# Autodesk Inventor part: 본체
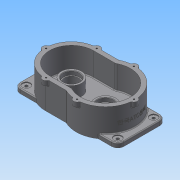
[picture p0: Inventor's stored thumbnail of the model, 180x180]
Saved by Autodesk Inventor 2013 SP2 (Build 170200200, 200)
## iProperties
Created: 2025-09
Part Number: 본체
Material: Generic
Document SubType Name: Modeling
Designer: a
Density: 1 g/cm^3
Author: a
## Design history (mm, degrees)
sketch "스케치1"
  geometry: L1 (-104.5, -55)-(104.5, -55); L2 (118.5, -41)-(118.5, 41); L3 (104.5, 55)-(-104.5, 55); L4 (-118.5, 41)-(-118.5, -41); L5 (-118.5, -55)-(118.5, 55); L6 (118.5, -55)-(-118.5, 55); A1 r 14 centre (-104.5, 41) between (-104.5, 55) and (-118.5, 41); A2 r 14 centre (104.5, 41) between (118.5, 41) and (104.5, 55); A3 r 14 centre (104.5, -41) between (104.5, -55) and (118.5, -41); A4 r 14 centre (-104.5, -41) between (-118.5, -41) and (-104.5, -55); 1 further point
  constraints: 12 end point, 8 point on circle, 8 point on line, 8 tangent, 4 centre point, 2 equal radius, 2 midpoint, 2 parallel, 1 horizontal, 1 perpendicular
  dimensions: "d0" = 237 distance of L5.end L6.end; "d2" = 110 distance of L6.start L5.end; "d3" = 14 radius of A1; "d4" = 14 radius of A2
extrude "돌출1" new body sketch "스케치1" distance "d5" = 10; taper "d6" = 0 deg
sketch "스케치2"
  geometry: L1 (118.5, 41)-(118.5, -41) reference; L2 (104.5, -55)-(-104.5, -55) reference; L3 (-118.5, -41)-(-118.5, 41) reference; L4 (-104.5, 55)-(104.5, 55) reference; L5 (-42.5, 50)-(8.132, 50); L6 (-42.5, -50)-(8.132, -50); L7 (-42.5, 60)-(5.684, 60); L8 (5.684, -60)-(-42.5, -60); A1 r 14 centre (104.5, 41) between (118.5, 41) and (104.5, 55) reference; A2 r 14 centre (104.5, -41) between (104.5, -55) and (118.5, -41) reference; A3 r 14 centre (-104.5, -41) between (-118.5, -41) and (-104.5, -55) reference; A4 r 14 centre (-104.5, 41) between (-104.5, 55) and (-118.5, 41) reference; A5 r 57 centre (35.5, 0) between (8.132, -50) and (8.132, 50); A6 r 50 centre (-42.5, 0) between (-42.5, 50) and (-42.5, -50); A7 r 60 centre (-42.5, 0) between (-42.5, 60) and (-42.5, -60); A8 r 67 centre (35.5, 0) between (5.684, -60) and (5.684, 60); 1 further point
  constraints: 8 end point, 8 point on circle, 4 centre point, 3 parallel, 2 horizontal alignment, 2 tangent, 3 other
  dimensions: "d7" = 114 diameter of A5; "d10" = 100 diameter of A6; "d11" = 76 distance from line of A6.centre L3; "d12" = 78 distance of A5.centre A6.centre; "d13" = 10 distance between parallel lines of L7 L5
  node "절단 모서리 투영1"
extrude "돌출2" join sketch "스케치2" distance "d14" = 64; taper "d15" = 0 deg
sketch "스케치3"
  geometry: L1 (8.132, 50)-(-42.5, 50) reference; L2 (-42.5, -50)-(8.132, -50) reference; L3 (118.5, 41)-(118.5, -41) reference; L4 (104.5, -55)-(73.762, -55) reference; L5 (5.684, -60)-(-42.5, -60) reference; L6 (-66.479, -55)-(-104.5, -55) reference; L7 (-118.5, -41)-(-118.5, 41) reference; L8 (-104.5, 55)-(-66.479, 55) reference; L9 (73.762, 55)-(104.5, 55) reference; L10 (-42.5, 60)-(5.684, 60) reference; L11 (50.467, -55)-(20.533, -55) reference; L12 (20.533, 55)-(50.467, 55) reference; C1 r 23.5 at (-42.5, 0); C2 r 23.5 at (35.5, 0); A1 r 50 centre (-42.5, 0) between (-42.5, 50) and (-42.5, -50) reference; A2 r 14 centre (104.5, 41) between (118.5, 41) and (104.5, 55) reference; A3 r 14 centre (104.5, -41) between (104.5, -55) and (118.5, -41) reference; A4 r 67 centre (35.5, 0) between (5.684, -60) and (73.762, -55) reference; A5 r 60 centre (-42.5, 0) between (-66.479, -55) and (-42.5, -60) reference; A6 r 14 centre (-104.5, -41) between (-118.5, -41) and (-104.5, -55) reference; A7 r 14 centre (-104.5, 41) between (-104.5, 55) and (-118.5, 41) reference; A8 r 60 centre (-42.5, 0) between (-66.479, 55) and (-66.479, -55) reference; A9 r 67 centre (35.5, 0) between (73.762, 55) and (5.684, 60) reference; A10 r 60 centre (-42.5, 0) between (-42.5, 60) and (-66.479, 55) reference; A11 r 67 centre (35.5, 0) between (73.762, -55) and (73.762, 55) reference; A12 r 57 centre (35.5, 0) between (8.132, -50) and (20.533, -55) reference; A13 r 57 centre (35.5, 0) between (20.533, -55) and (50.467, -55) reference; A14 r 57 centre (35.5, 0) between (50.467, -55) and (50.467, 55) reference; A15 r 57 centre (35.5, 0) between (50.467, 55) and (20.533, 55) reference; A16 r 57 centre (35.5, 0) between (20.533, 55) and (8.132, 50) reference; 1 further point
  constraints: 2 centre point, 2 coincident
  dimensions: "d16" = 47 diameter of C1; "d17" = 47 diameter of C2
  node "절단 모서리 투영2"
extrude "돌출3" join sketch "스케치3" distance "d18" = 12; taper "d19" = 0 deg
extrude "돌출4" join sketch "스케치2" distance "d20" = 10; taper "d21" = 0 deg
extrude "돌출5" join sketch "스케치3" distance "d22" = 26; taper "d23" = 0 deg
hole "구멍1" diameter "d26" = 6.6; stored, may be unused: countersink angle "d30" = 90 deg, drill point angle "d32" = 118 deg; dims "d24" = 10, "d25" = 10, "d27" = 6, "d28" = 18, "d29" = 2, "d31" = 8
hole "구멍2" diameter "d35" = 6.6; stored, may be unused: countersink angle "d39" = 90 deg, drill point angle "d41" = 118 deg; dims "d33" = 10, "d34" = 10, "d36" = 6, "d37" = 18, "d38" = 2, "d40" = 8
hole "구멍3" diameter "d44" = 6.6; stored, may be unused: countersink angle "d48" = 90 deg, drill point angle "d50" = 118 deg; dims "d42" = 10, "d43" = 10, "d45" = 6, "d46" = 18, "d47" = 2, "d49" = 8
hole "구멍4" diameter "d53" = 6.6; stored, may be unused: countersink angle "d57" = 90 deg, drill point angle "d59" = 118 deg; dims "d51" = 10, "d52" = 10, "d54" = 6, "d55" = 18, "d56" = 2, "d58" = 8
hole "구멍5" diameter "d62" = 32; stored, may be unused: countersink angle "d66" = 90 deg, drill point angle "d68" = 0 deg; dims "d63" = 6, "d64" = 37, "d65" = 9, "d67" = 16, "d69" = 10, "d70" = 10
hole "구멍6" diameter "d73" = 28; stored, may be unused: countersink angle "d77" = 90 deg, drill point angle "d79" = 0 deg; dims "d71" = 10, "d72" = 10, "d74" = 6, "d75" = 4, "d76" = 2, "d78" = 3
hole "구멍7" diameter "d82" = 28; stored, may be unused: countersink angle "d86" = 90 deg, drill point angle "d88" = 0 deg; dims "d80" = 10, "d81" = 10, "d83" = 6, "d84" = 37, "d85" = 9, "d87" = 30
hole "구멍8" diameter "d91" = 35; stored, may be unused: countersink angle "d95" = 90 deg, drill point angle "d97" = 0 deg; dims "d89" = 10, "d90" = 10, "d92" = 6, "d93" = 37, "d94" = 9, "d96" = 8.3
chamfer "모따기1" distance "d98" = 0.8; stored, may be unused: second distance "d99" = 2, angle "d100" = 30 deg
fillet "모깎기1" dims "d101" = 0.3
chamfer "모따기2" distance "d102" = 1; stored, may be unused: second distance "d103" = 2, angle "d104" = 45 deg
sketch "스케치4"
  geometry: C1 r 8 at (-100.5, 0); C2 r 8 at (-42.5, 58); C3 r 8 at (-42.5, -58); C4 r 8 at (35.5, -65); C5 r 8 at (35.5, 65); C6 r 8 at (100.5, 0); A1 r 57 centre (35.5, 0) between (8.132, -50) and (8.132, 50) reference; A2 r 50 centre (-42.5, 0) between (-42.5, 50) and (-42.5, -50) reference; A3 r 67 centre (35.5, 0) between (5.684, -60) and (5.684, 60) reference; 1 further point
  constraints: 6 centre point, 3 vertical alignment, 2 horizontal alignment
  dimensions: "d105" = 16 diameter of C1; "d106" = 16 diameter of C2; "d107" = 16 diameter of C3; "d108" = 16 diameter of C5; "d109" = 16 diameter of C6; "d110" = 16 diameter of C4; "d111" = 116 distance of C3.centre C2.centre; "d112" = 58 distance of A2.centre C3.centre; "d113" = 58 distance of A2.centre C1.centre; "d114" = 78 horizontal distance of C3.centre C4.centre; "d115" = 130 distance of C5.centre C4.centre; "d116" = 65 distance of C5.centre A1.centre; "d117" = 65 distance of A1.centre C6.centre
extrude "돌출6" join sketch "스케치4" distance "d118" = 12; taper "d119" = 0 deg
hole "구멍9" diameter "d122" = 3.242; stored, may be unused: countersink angle "d126" = 90 deg, drill point angle "d128" = 118 deg; dims "d120" = 10, "d121" = 10, "d123" = 8, "d124" = 37, "d125" = 9, "d127" = 10
hole "구멍10" diameter "d131" = 3.242; stored, may be unused: countersink angle "d135" = 90 deg, drill point angle "d137" = 118 deg; dims "d129" = 10, "d130" = 10, "d132" = 8, "d133" = 37, "d134" = 9, "d136" = 10
hole "구멍11" diameter "d140" = 3.242; stored, may be unused: countersink angle "d144" = 90 deg, drill point angle "d146" = 118 deg; dims "d138" = 10, "d139" = 10, "d141" = 8, "d142" = 37, "d143" = 9, "d145" = 10
hole "구멍12" diameter "d149" = 3.242; stored, may be unused: countersink angle "d153" = 90 deg, drill point angle "d155" = 118 deg; dims "d147" = 10, "d148" = 10, "d150" = 8, "d151" = 37, "d152" = 9, "d154" = 10
hole "구멍13" diameter "d158" = 3.242; stored, may be unused: countersink angle "d162" = 90 deg, drill point angle "d164" = 118 deg; dims "d156" = 10, "d157" = 10, "d159" = 8, "d160" = 37, "d161" = 9, "d163" = 10
hole "구멍14" diameter "d167" = 3.242; stored, may be unused: countersink angle "d171" = 90 deg, drill point angle "d173" = 118 deg; dims "d165" = 10, "d166" = 10, "d168" = 8, "d169" = 37, "d170" = 9, "d172" = 10
sketch "스케치6"
  geometry: L1 (0, 82)-(0, 0) reference; L2 (-10, 0)-(-10, 82) reference; L3 (0, 82)-(-10, 82) reference; L4 (0, 82)-(0, 0) reference; L5 (0, 0)-(-10, 0) reference; L6 (-40, 5)-(-40, 77); L7 (-40, 77)-(-20, 77); L8 (-20, 77)-(-20, 5); L9 (-20, 5)-(-40, 5); 3 further points
  constraints: 2 midpoint, 1 horizontal alignment, 1 parallel, 2 other
  dimensions: "d174" = 20 distance of L8.end L6.start; "d176" = 20 horizontal distance of point (0, 41) L8.end; "d177" = 72 distance of L6.start L6.end
feature "엠보싱1" sketch "스케치6" dims "d0" = 237, "d2" = 110, "d3" = 14, "d4" = 14, "d7" = 114, "d178" = 0.5, "d179" = 0
fillet "모깎기2" dims "d180" = 2
fillet "모깎기3" dims "d181" = 13
fillet "모깎기4" dims "d182" = 2
node "솔리드1"
node "절단 모서리 투영4"
